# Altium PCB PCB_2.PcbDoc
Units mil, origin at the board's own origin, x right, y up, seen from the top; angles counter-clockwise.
Board outline 5950 x 2265 mil, 6 copper layers (Top Layer 3, Top Layer 2, Top Layer 1, Bottom Layer 1, Bottom Layer 2, Bottom Layer 3), stack 32.068 mil thick; 9 components, 19 nets, 173 pads, 11 vias.
Unrouted connection lines stored in the file: 1.
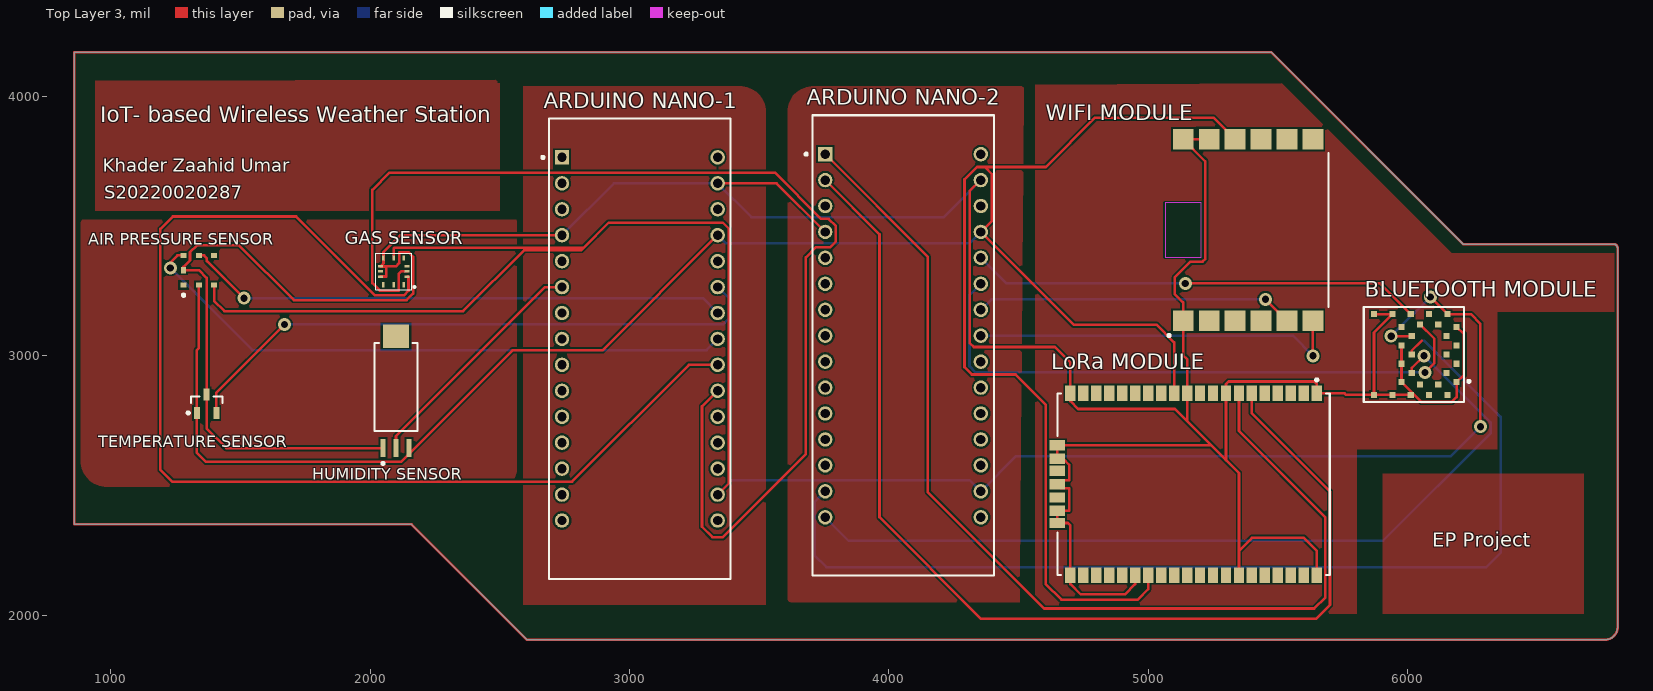
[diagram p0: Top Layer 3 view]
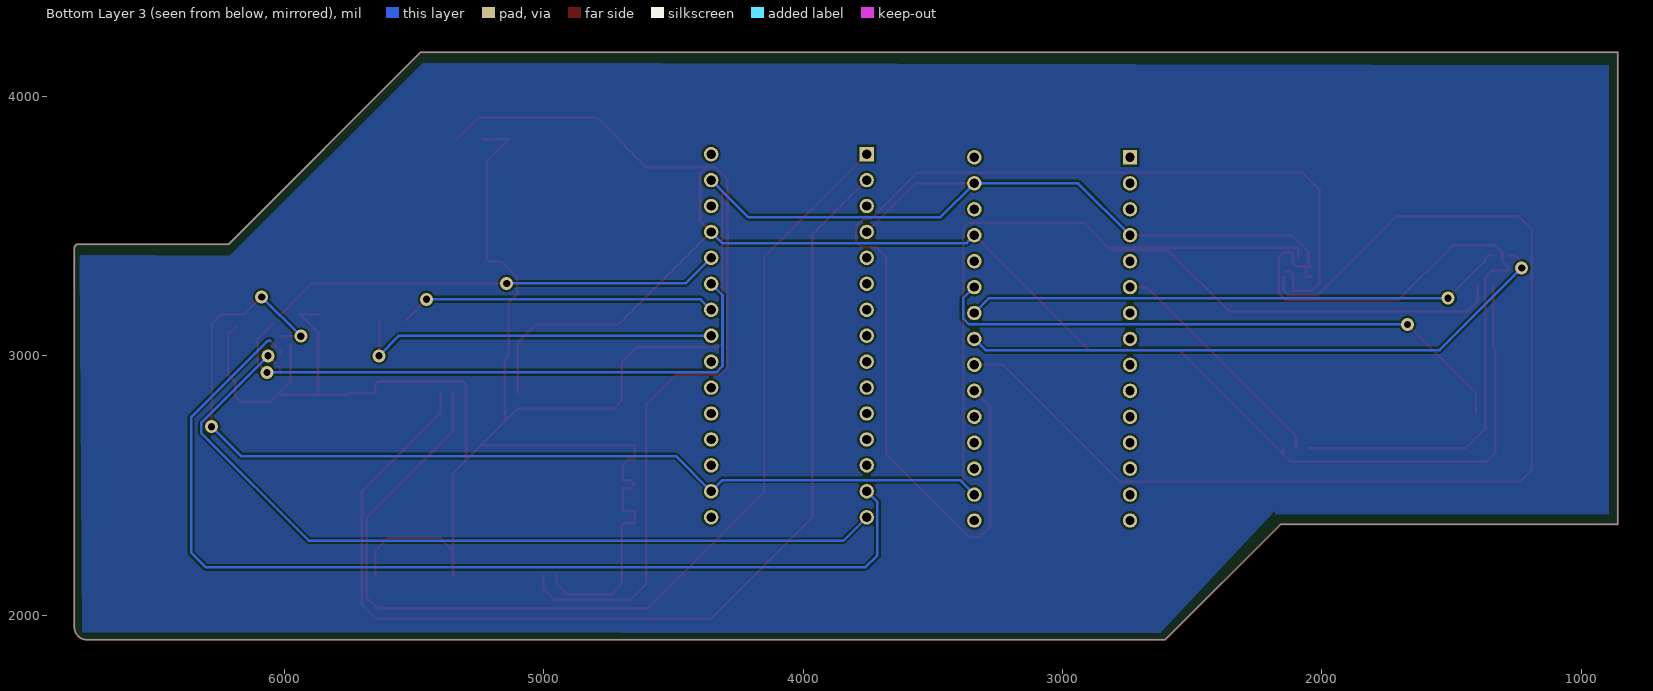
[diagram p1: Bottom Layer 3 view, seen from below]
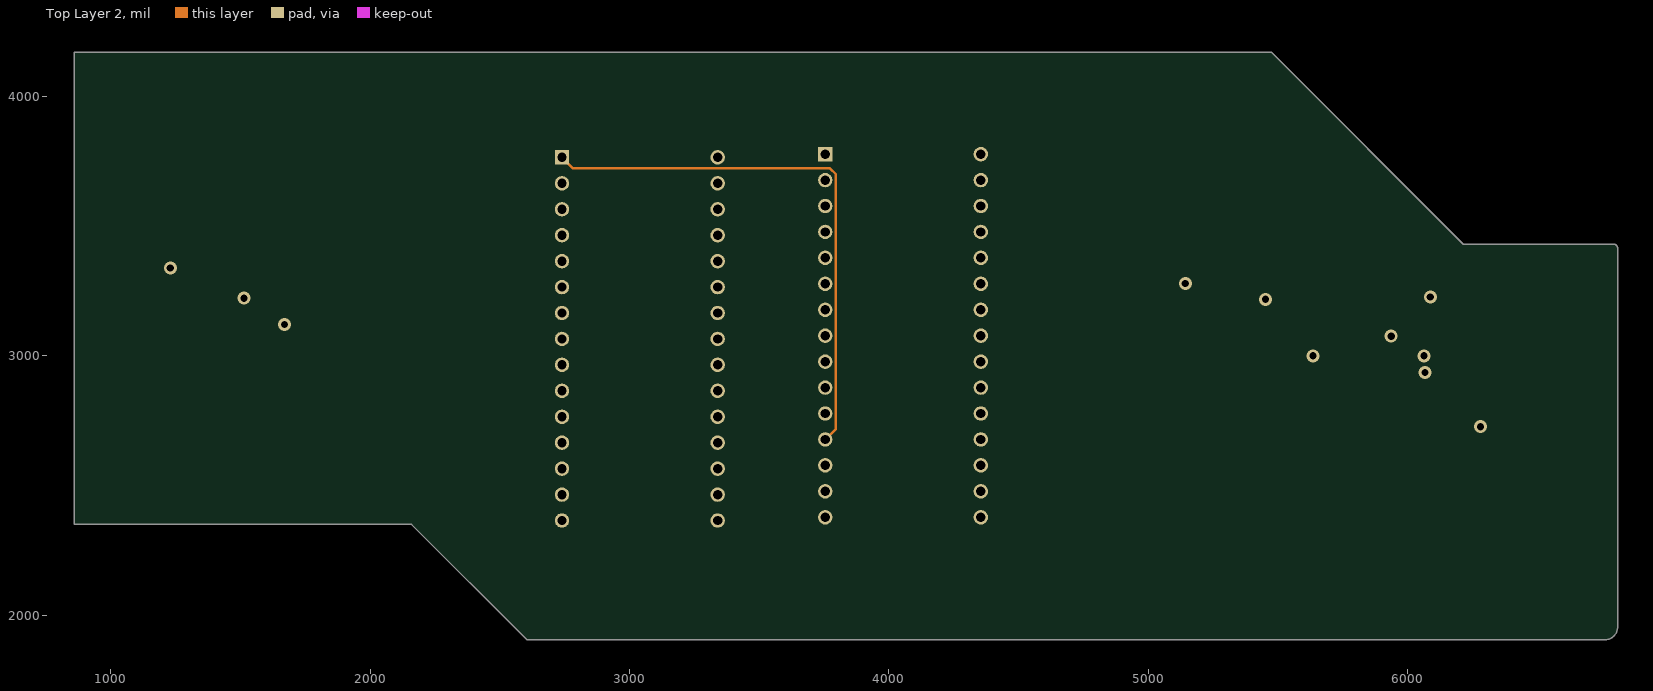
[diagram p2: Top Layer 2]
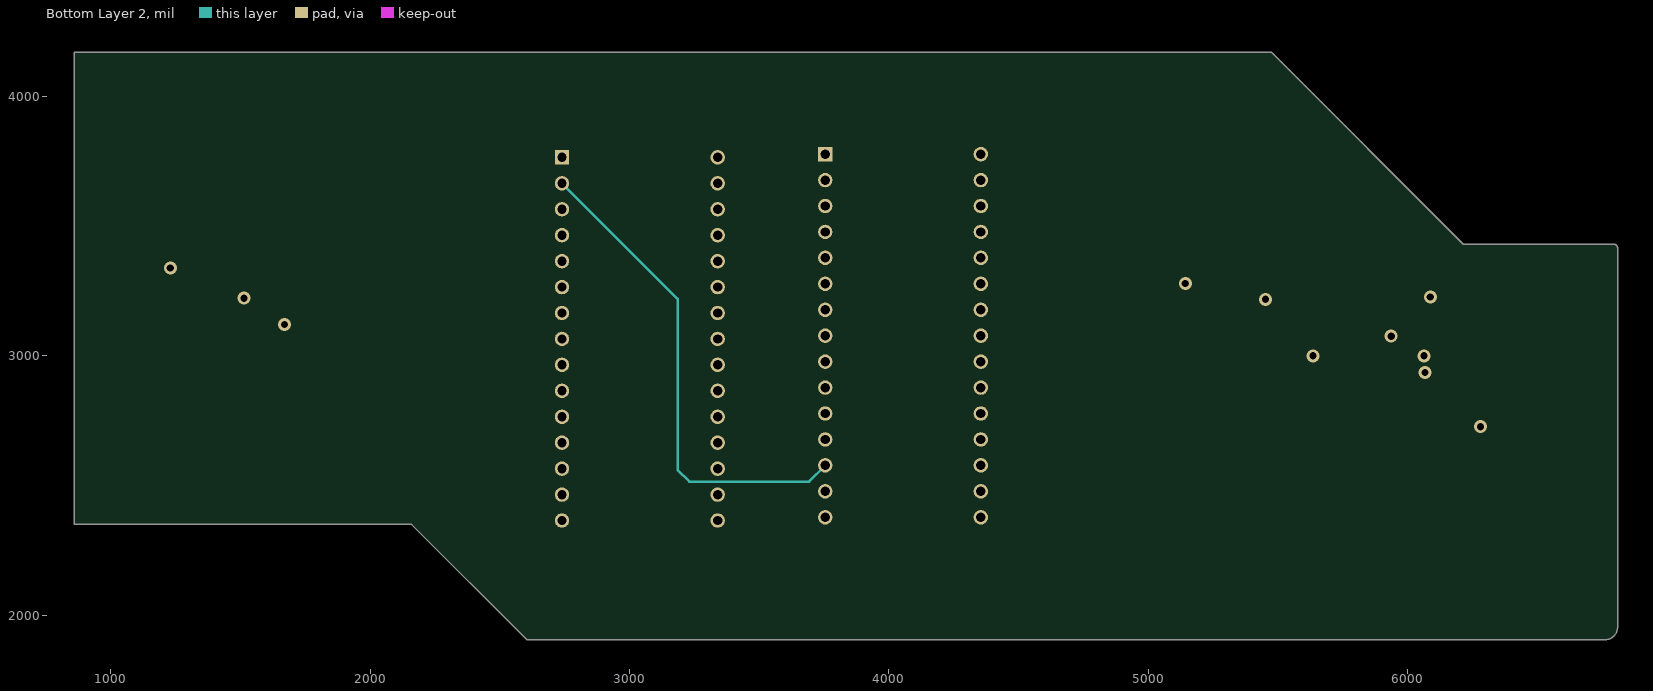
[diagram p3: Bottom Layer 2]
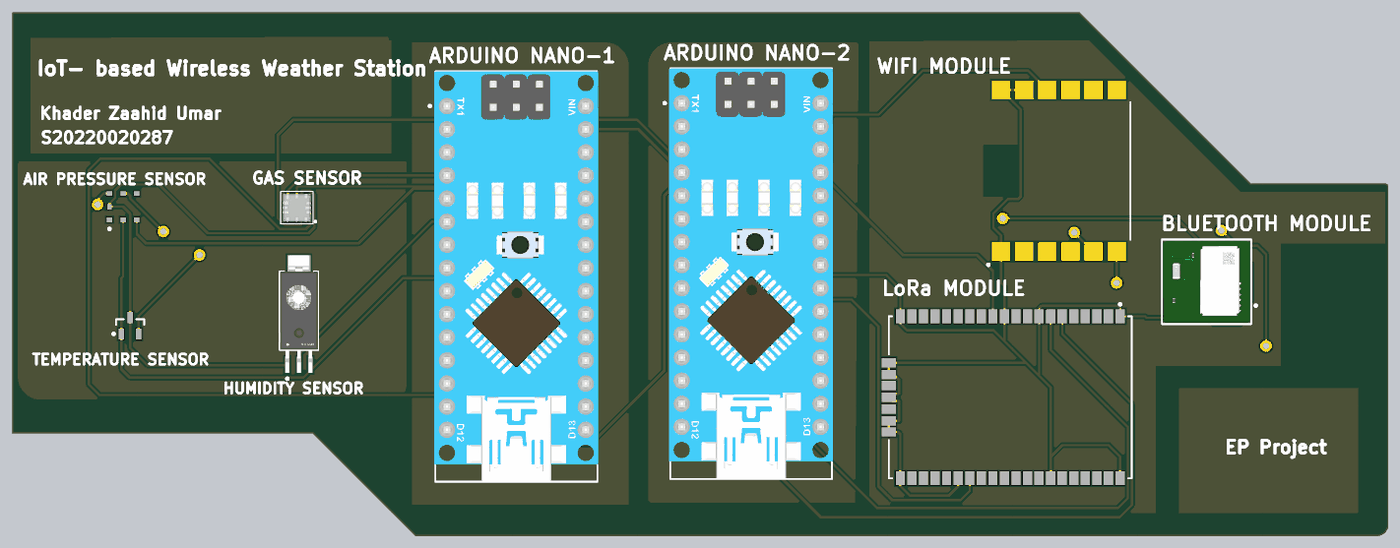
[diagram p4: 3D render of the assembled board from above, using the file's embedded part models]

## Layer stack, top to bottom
Top Solder: solder mask 1, SM-002, Dk 4
Top Layer 3: signal copper 1.378
Dielectric 6: prepreg 2.8, PP-006, Dk 4.1
Top Layer 2: signal copper 1.378
Dielectric 4: prepreg 2.8, PP-006, Dk 4.1
Top Layer 1: signal copper 1.378
Dielectric 1: dielectric 12.6, FR-4, Dk 4.8
Bottom Layer 1: signal copper 1.378
Dielectric 5: prepreg 2.8, PP-006, Dk 4.1
Bottom Layer 2: signal copper 1.378
Dielectric 7: prepreg 2.8, PP-006, Dk 4.1
Bottom Layer 3: signal copper 1.378
Bottom Solder: solder mask 1, SM-002, Dk 4

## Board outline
2160,2350 2605,1905 6760,1905 ccw(c6760,1955) 6810,1955 6810,3415 ccw(c6795,3415) 6795,3430 6215,3430 5475,4170 860,4170 860,2350

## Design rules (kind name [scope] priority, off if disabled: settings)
Clearance [All] p1: gap=8 ignorepadtopadclearanceinfootprint=FALSE
PolygonConnect [All] p1: connectstyle=Relief reliefconductorwidth=10 reliefentries=4 polygonreliefangle="90 Angle" airgapwidth=10
RoutingVias [All] p1: holewidth=28 width=50 viastyle="Through Hole" minholewidth=28 minwidth=50 maxholewidth=28 maxwidth=50
SolderMaskExpansion [All] p1: expansion=4 istentingtop=FALSE
SupplyNets "Schematic Supply Nets_2" [InNet('+5V')] p1: voltage=0.000
SupplyNets "Schematic Supply Nets_1" [InNet('GND')] p2: voltage=0.000
SupplyNets "Schematic Supply Nets" [InNet('3V3')] p3: voltage=0.000
Width [All] p1: maxlimit=10 minlimit=10 preferedwidth=10
30 further rules are at their usual default settings.

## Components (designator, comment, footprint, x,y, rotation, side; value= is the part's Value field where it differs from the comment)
"AIR PRESSURE SENSOR" "BMP180" BOSC-BMP180-7_V 1340,3330 r90 top
"ARDUINO NANO-1" "A000005" FP-A000005-MFG 3040,3027.5 r0 top
"ARDUINO NANO-2" "A000005" FP-A000005-MFG 4055,3040 r0 top
"BLUETOOTH MODULE" "ENW-89846A1KF" FP-ENW-89846A1KF-MFG 6024.02,3005 r90 top
"GAS SENSOR" "ZMOD4510AI1V" "ZMODxxxx 12 Leads- LGG12" 2091.18,3325.32 r90 top
"HUMIDITY SENSOR" "HIH-5031-001" FP-HIH-5031-001-MFG 2100,2880 r0 top
"LoRa MODULE" "RN2483-I/RM095" MCHP-RN2483-47_V 5175,2505 r90 top
"TEMPERATURE SENSOR" "TC1047AVNBTR" SOT-23-NB3_L 1370,2815 r90 top
"WIFI MODULE" "MRF24J40MA-I/RM" MRF24J40MA 5065,3485 r90 top

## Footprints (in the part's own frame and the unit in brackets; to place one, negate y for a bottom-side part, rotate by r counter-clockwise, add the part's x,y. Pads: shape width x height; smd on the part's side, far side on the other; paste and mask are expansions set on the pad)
BOSC-BMP180-7_V [mm] "LGA, 7-Leads, Body 3.9x3.8mm, Pitch 1.5mm"
  rect 0.5x0.6 smd: 1(-1.45,1.5) 2(-1.45,0) 3(-1.45,-1.5) 4(1.45,-1.5) 5(1.45,0) 6(1.45,1.5)
  rect 0.6x0.5 smd: 7(0,1.5)
  silkscreen extent -2.57,1.37 -2.33,1.62, body extent -1.85,-1.95 1.85,1.95, height 1
FP-A000005-MFG [mil]
  rect 55.67x55.67 hole 35.98 paste-99999 mask+0: 1(-300,737.5)
  round 55.67 hole 35.98 paste-99999 mask+0: 2(-300,637.5) 3(-300,537.5) 4(-300,437.5) 5(-300,337.5) 6(-300,237.5) 7(-300,137.5) 8(-300,37.5) 9(-300,-62.5) 10(-300,-162.5) 11(-300,-262.5) 12(-300,-362.5) 13(-300,-462.5) 14(-300,-562.5) 15(-300,-662.5) 16(300,-662.5) 17(300,-562.5) 18(300,-462.5) 19(300,-362.5) 20(300,-262.5) 21(300,-162.5) 22(300,-62.5) 23(300,37.5) 24(300,137.5) 25(300,237.5) 26(300,337.5) 27(300,437.5) 28(300,537.5) 29(300,637.5) 30(300,737.5)
  silkscreen extent -379,-888 350,888, body extent -354,-891 354,891, height 10
FP-ENW-89846A1KF-MFG [mm]
  rect 0.6x0.6 smd paste+0 mask+0: 1(-2.7,-4.2) 2(-1.8,-3.2) 3(-0.9,-4.2) 4(0,-3.2) 5(0.9,-4.2) 6(1.8,-3.2) 7(2.7,-4.2) 8(3.95,-3.3) 9(2.95,-2.4) 10(3.95,-1.5) 11(2.95,-0.6) 12(3.95,0.3) 13(2.7,1.2) 14(1.8,0.2) 15(0.9,1.2) 16(0,0.2) 17(-0.9,1.2) 18(-1.8,0.2) 19(-2.7,1.2) 20(-3.95,0.3) 21(-2.95,-0.6) 22(-3.95,-1.5) 23(-2.95,-2.4) 24(-3.95,-3.3) A(-3.95,2.1) B(3.95,2.1) C(-3.95,3.9) D(3.95,3.9)
  silkscreen extent -4.65,-5.53 4.65,4.9, body extent -4.75,-5 4.75,5, height 0.25
FP-HIH-5031-001-MFG [mm]
  rect 0.51x1.78 smd paste+0 mask+0: 1(-1.27,-5.97) 2(0,-5.97) 3(1.27,-5.97)
  rect 2.54x2.29 smd paste+0 mask+0: 4(0,4.955)
  silkscreen extent -2.11,-7.6 2.11,4.32, body extent -2.21,-6.96 2.21,6.2, height 0.25
MCHP-RN2483-47_V [mil] "47-Leads, Body 26.67x17.8mm, Pitch 1.27mm"
  rect 60x40 smd mask+3.94: 1(350.39,-475) 2(350.39,-425) 3(350.39,-375) 4(350.39,-325) 5(350.39,-275) 6(350.39,-225) 7(350.39,-175) 8(350.39,-125) 9(350.39,-75) 10(350.39,-25) 11(350.39,25) 12(350.39,75) 13(350.39,125) 14(350.39,175) 15(350.39,225) 16(350.39,275) 17(350.39,325) 18(350.39,375) 19(350.39,425) 20(350.39,475) 28(-350.39,475) 29(-350.39,425) 30(-350.39,375) 31(-350.39,325) 32(-350.39,275) 33(-350.39,225) 34(-350.39,175) 35(-350.39,125) 36(-350.39,75) 37(-350.39,25) 38(-350.39,-25) 39(-350.39,-75) 40(-350.39,-125) 41(-350.39,-175) 42(-350.39,-225) 43(-350.39,-275) 44(-350.39,-325) 45(-350.39,-375) 46(-350.39,-425) 47(-350.39,-475)
  rect 40x60 smd mask+3.94: 21(149.61,525) 22(98.43,525) 23(51.18,525) 24(0,525) 25(-51.18,525) 26(-102.36,525) 27(-149.61,525)
  silkscreen extent -350,-525 407,525, body extent -350,-525 350,525, height 118
MRF24J40MA [mil] "SM Module; 12 Leads; Body 27.9x17.8x1.7mm (LxWxH), Microchip Recommended"
  rect 80x80 smd paste-159.45 mask+2: 1(-350,-70) 2(-350,-170) 3(-350,-270) 4(-350,-370) 5(-350,-470) 6(-350,-570) 7(350,-570) 8(350,-470) 9(350,-370) 10(350,-270) 11(350,-170) 12(350,-70)
  Top Layer 3 keep-out region: -105,-140 105,-140 105,0 -105,0
  silkscreen extent -411,-630 298,-11, body extent -350,-630 350,470, height 67
SOT-23-NB3_L [mm] "SOT23, 3-Leads, Body 2.9x1.3mm, Pitch 0.95mm, Lead Span 2.4mm, IPC High Density"
  rect 1.2x0.6 smd: 1(-0.9,0.95) 2(-0.9,-0.95) 3(0.9,0)
  silkscreen extent -1.02,-1.55 0.7,1.92, body extent -0.7,-1.52 0.7,1.53, height 1.12
"ZMODxxxx 12 Leads- LGG12" [mm] "LGA 3.00x3.00x0.70 mm 0.50mm Pitch"
  rect 0.25x0.5 smd: 1(-0.5,-1.3) 2(0,-1.3) 3(0.5,-1.3) 7(0.5,1.3) 8(0,1.3) 9(-0.5,1.3)
  rect 0.5x0.25 smd: 4(1.3,-1) 5(1.3,0) 6(1.3,1) 10(-1.3,1) 11(-1.3,0) 12(-1.3,-1)
  silkscreen extent -1.78,-2.13 1.78,1.78, body extent -1.5,-1.5 1.5,1.5, height 0.78

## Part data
"AIR PRESSURE SENSOR": library part CMP-2000-05074-1, "Digital Pressure Sensor, 1.8 to 3.6 V, -40 to 85 degC, 7-Pin LGA, RoHS", Manufacturer="Bosch Sensortec", Operating Pressure=4.35PSI~15.95PSI(30kPa~110kPa), Operating Temperature=-40degC~85degC, Package / Case=7-VLGA, Standard Package=5,000, Supplier Device Package=7-LGA, Voltage - Supply=1.62V~3.6V
"ARDUINO NANO-1" "ARDUINO NANO-2": library part CMP-189986-000002-1, "ARDUINO NANO ATMEGA328 EVAL BRD", Operating Supply Voltage=12V, Package Quantity=50
"BLUETOOTH MODULE": library part CMP-05527-000002-1, "RF TXRX MOD BLUETOOTH CHIP ANT", Ambient Temperature Range High=+85°C, Ambient Temperature Range Low=-40°C, Manufacturer=Panasonic, Max Frequency=2.4GHz, Max Supply Voltage=3.3V, Min Supply Voltage=2.35V, Package=0, Receiving Current=4.9mA, Temperature="-40°C to +85°C"
"GAS SENSOR": library part CMP-00572-100129191-1, "ZMOD4510AI1V ZMOD4510 Series 3.6 V 11 mA Gas Sensor Module for Outdoor Air Quality - LGA-12"
"HUMIDITY SENSOR": library part CMP-11179-000003-1, "SENSOR HUMIDITY 5V ANALOG 3% SMD", Case/Package=SMD/SMT, Max Operating Temperature=85°C, Max Supply Voltage=5.5V, Min Operating Temperature=-40°C, Min Supply Voltage=2.7V, Nominal Supply Current=500uA, Operating Supply Current=200uA, Operating Supply Voltage=3.3V, Package Quantity=1
"LoRa MODULE": library part CMP-2000-05219-1, "Low-Power Long Range LoRa(TM) Technology Transceiver Module, 2.1 to 3.6 V, -40 to 85 degC, 47-Pin SMD, RoHS", Manufacturer=Microchip, Maximum Operating Supply Voltage=3.6V, Maximum Operating Temperature=+85degC, Minimum Operating Supply Voltage=2.1V, Minimum Operating Temperature=-40degC, Operating Band Frequency Range=438,868MHz, Operating Supply Voltage Range=2.1to3.6V, Operating Temperature Range=-40to+85degC, Package Type=Module
"TEMPERATURE SENSOR": library part CMP-0192-00223-1, "Precision Temperature-to-Voltage Converter, 3-Pin SOT-23, Extended Temperature, Tape and Reel"
"WIFI MODULE": library part CMP-0191-00063-1, "2.4 GHz IEEE Std. 802.15.4, RF Transceiver 12-Pin Module, Industrial Temperature"

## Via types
v1: diameter 50, hole 28, Top Layer 3 to Bottom Layer 3, 11 vias

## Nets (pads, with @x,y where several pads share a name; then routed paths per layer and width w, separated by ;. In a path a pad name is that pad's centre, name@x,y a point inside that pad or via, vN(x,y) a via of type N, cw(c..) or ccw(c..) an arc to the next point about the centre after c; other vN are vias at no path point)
3V3: "AIR PRESSURE SENSOR.3" "ARDUINO NANO-1.17" "ARDUINO NANO-2.17" "BLUETOOTH MODULE.8" "BLUETOOTH MODULE.14" "GAS SENSOR.5" | length 8038
  Top Layer 3 w10: 1399.06,3272.91 1399.06,3211 1438.06,3172 2359,3172 2595,3408 2815,3408 2824.34,3417.34 ; 2091.18,3376.5 2091.18,3413.89 2094.63,3417.34 2824.34,3417.34 ; 3340,2465 3383,2508 3383,3490 3360,3513 2920,3513 2824.34,3417.34 ; v1(5937,3075.87) 6016.14,3075.87 ; v1(6087.79,3226.66) 6153.94,3160.51 6244,3160.51 6281,3123.51 v1(6281,2727)
  Bottom Layer 3 w10: 3340,2465 3396,2521 4311.5,2521 4355,2477.5 4490.5,2613 6167,2613 v1(6281,2727) ; v1(5937,3075.87) v1(6087.79,3226.66)
+5V: "AIR PRESSURE SENSOR.2" "ARDUINO NANO-1.27" "ARDUINO NANO-2.27" "HUMIDITY SENSOR.3" "LoRa MODULE.12" "LoRa MODULE.34" "TEMPERATURE SENSOR.1" "WIFI MODULE.10" | length 8955.6
  Top Layer 3 w10: 1340,3272.91 1340,3029.4 1332.6,3022 1332.6,2779.57 1332.6,2626 1367.6,2591 2119,2591 2150,2622 ; 2150,2644.96 2150,2622 ; 3340,3465 2896,3021 2549,3021 2161.48,2633.48 2150,2622 ; 5000,2154.61 5000,2100 4960,2060 4665,2060 4605,2120 4605,2812 4489,2928 4320,2928 4292,2956 4292,3680 4340,3728 4370,3728 ; 5100,2855.39 5100,3052 5032,3120 4712.5,3120 4355,3477.5 4398,3520.5 4398,3700 4370,3728 ; 5335,3835 5252,3918 4795.5,3918 4605.5,3728 4370,3728
  Bottom Layer 3 w10: 3340,3465 3370.34,3434.66 4312.16,3434.66 4355,3477.5
GND: "AIR PRESSURE SENSOR.7" "ARDUINO NANO-1.4" "ARDUINO NANO-1.29" "ARDUINO NANO-2.4" "ARDUINO NANO-2.29" "BLUETOOTH MODULE.1" "BLUETOOTH MODULE.7" "BLUETOOTH MODULE.15" "BLUETOOTH MODULE.17" "BLUETOOTH MODULE.19" "BLUETOOTH MODULE.20" "BLUETOOTH MODULE.A" "BLUETOOTH MODULE.B" "BLUETOOTH MODULE.C" "BLUETOOTH MODULE.D" "GAS SENSOR.6" "GAS SENSOR.7" "GAS SENSOR.9" "HUMIDITY SENSOR.1" "LoRa MODULE.1" "LoRa MODULE.8" "LoRa MODULE.11" "LoRa MODULE.20" "LoRa MODULE.21" "LoRa MODULE.22" "LoRa MODULE.24" "LoRa MODULE.26" "LoRa MODULE.27" "LoRa MODULE.28" "LoRa MODULE.33" "LoRa MODULE.41" "LoRa MODULE.47" "TEMPERATURE SENSOR.3" "WIFI MODULE.1" "WIFI MODULE.11" "WIFI MODULE.12" | length 13850.3
  Top Layer 3 w10: 2040,3305.63 2063,3305.63 2063,3344 2041,3344 2040,3345 ; 2050,2644.96 2050,2644 1446,2644 1370,2720 1370,2850.43 1370,3300 1340,3330 1280.94,3330 1280.94,3342.94 1306,3368 1306,3400 1332,3426 1495,3426 1706,3215 2141.47,3215 2166.47,3240 2166.47,3380.87 2148,3399.34 2112,3399.34 2112,3357 2100,3345 2040,3345 ; 2740,3465 2116.81,3465 2051.81,3400 2051.81,3376.5 2051.81,3356.81 2040,3345 ; 3340,3665 3567.5,3665 3755,3477.5 ; 4355,3677.5 4312,3634.5 4312,3050 4328,3034 4640,3034 4700,2974 4700,2855.39 4700,2825 4730,2795 5103,2795 5150,2748 ; 4950,2154.61 4950,2120 4910,2080 4740,2080 4700,2120 4700,2154.61 4700,2345.39 4690,2355.39 4650,2355.39 4650,2402.64 4695,2402.64 4695,2489 4666,2489 4650,2505 4666,2521 4695,2521 4695,2580 4671.57,2603.43 4650,2603.43 4650,2654.61 5243.39,2654.61 ; 5235,3835 5135,3835 5220,3750 5220,3373 5210,3363 5163.99,3363 5102.37,3301.38 5102.37,3239.01 5135,3206.38 5135,3135 5135,3002 5150,2987 5150,2855.39 5150,2748 ; 5350,2154.61 5350,2248 ; 5650,2154.61 5650,2248 5600,2298 5400,2298 5350,2248 ; 5870.47,3160.51 5941.34,3160.51 5870.47,3089.65 5870.47,2849.49 ; 5976.77,3040.43 5976.77,2969.57 5976.77,2898.7 6019.09,2856.38 ; 6189.37,3111.3 6217,3083.67 6217,2926.33 6189.37,2898.7 6189.37,2841.37 6170,2822 6053.47,2822 6019.09,2856.38 ; 5150,2748 5243.39,2654.61 ; 5243.39,2654.61 5300,2598 ; 5300,2598 5350,2548 5350,2248 ; 5300,2598 5300,2855.39 5300,2891 5310,2901 5640,2901 5650,2891 5650,2855.39 5757,2855.39 5762.91,2849.49 5870.47,2849.49 ; 5870.47,2849.49 5941.34,2849.49 6012.2,2849.49 6019.09,2856.38
  Bottom Layer 3 w10: 2740,3465 2940,3665 3340,3665 3470.34,3534.66 4212.16,3534.66 4355,3677.5
"NetAIR PRESSURE SENSOR_5": "AIR PRESSURE SENSOR.5" "ARDUINO NANO-1.24" | length 2098.5
  Top Layer 3 w10: 1340,3387.09 1360,3387.09 1371,3376.09 1371,3365 v1(1514,3222)
  Bottom Layer 3 w10: v1(1514,3222) 3283,3222 3340,3165
"NetAIR PRESSURE SENSOR_6": "AIR PRESSURE SENSOR.6" "ARDUINO NANO-1.23" | length 2342.1
  Top Layer 3 w10: v1(1230,3339) 1230,3360 1257.09,3387.09 1280.94,3387.09
  Bottom Layer 3 w10: v1(1230,3339) 1546.84,3022.16 3297.16,3022.16 3340,3065
"NetARDUINO NANO-1_1": "ARDUINO NANO-1.1" "ARDUINO NANO-2.12" | length 2122.4
  Top Layer 2 w10: 2740,3765 2782,3723 3773,3723 3796,3700 3796,2718.5 3755,2677.5
"NetARDUINO NANO-1_2": "ARDUINO NANO-1.2" "ARDUINO NANO-2.13" | length 1903.3
  Bottom Layer 2 w10: 2740,3665 3186,3219 3186,2560 3231,2515 3692.5,2515 3755,2577.5
"NetARDUINO NANO-1_6": "ARDUINO NANO-1.6" "HUMIDITY SENSOR.2" | length 923.8
  Top Layer 3 w10: 2100,2644.96 2100,2691 2674,3265 2740,3265
"NetARDUINO NANO-1_21": "ARDUINO NANO-1.21" "GAS SENSOR.2" | length 4530.7
  Top Layer 3 w10: 2142.36,3325.32 2120,3325.32 2110,3315.32 2110,3251 2038,3251 2009,3280 2009,3640 2075,3706 3561,3706 3739,3528 3768,3528 3796,3500 3796,3440 3775,3419 3720,3419 3680,3379 3680,2621 3360,2301 3320,2301 3280,2341 3280,2805 3340,2865
"NetARDUINO NANO-1_22": "ARDUINO NANO-1.22" "GAS SENSOR.1" | length 4452.3
  Top Layer 3 w10: 2142.36,3305.63 2148.47,3305.63 2148.47,3251.29 2130.18,3233 2019,3233 1715,3537 1240,3537 1192,3489 1192,2560 1237,2515 2779,2515 3229,2965 3340,2965
"NetARDUINO NANO-1_25": "ARDUINO NANO-1.25" "TEMPERATURE SENSOR.2" | length 2311.3
  Top Layer 3 w10: 1407.4,2779.57 1407.4,2858 v1(1670.4,3121)
  Bottom Layer 3 w10: v1(1670.4,3121) 3360,3121 3383,3144 3383,3222 3340,3265
"NetARDUINO NANO-2_1": "ARDUINO NANO-2.1" "LoRa MODULE.7" | length 4127.2
  Top Layer 3 w10: 3755,3777.5 4150,3382.5 4150,2475 4599,2026 5640,2026 5683,2069 5683,2377 5350,2710 5350,2855.39
"NetARDUINO NANO-2_2": "ARDUINO NANO-2.2" "LoRa MODULE.6" | length 4247.9
  Top Layer 3 w10: 3755,3677.5 3964,3468.5 3964,2378 4356,1986 5647,1986 5701,2040 5701,2477 5400,2778 5400,2855.39
"NetARDUINO NANO-2_14": "ARDUINO NANO-2.14" "BLUETOOTH MODULE.16" | length 3969.7
  Top Layer 3 w10: 6016.14,3005 6016.14,3020 6054.14,3058
  Bottom Layer 3 w10: 3755,2477.5 3714,2436.5 3714,2231 3760,2185 6304,2185 6359,2240 6359,2764 6065,3058 6054.14,3058
"NetARDUINO NANO-2_15": "ARDUINO NANO-2.15" "BLUETOOTH MODULE.18" | length 3264.7
  Top Layer 3 w10: 6016.14,2934.13 6016.14,2953.14 v1(6063,3000)
  Bottom Layer 3 w10: 3755,2377.5 3845.5,2287 5906,2287 6320,2701 6320,2743 v1(6063,3000)
"NetARDUINO NANO-2_23": "ARDUINO NANO-2.23" "WIFI MODULE.6" | length 1447.1
  Top Layer 3 w10: v1(5635,3000) 5635,3135
  Bottom Layer 3 w10: 4355,3077.5 5557.5,3077.5 v1(5635,3000)
"NetARDUINO NANO-2_24": "ARDUINO NANO-2.24" "WIFI MODULE.5" | length 1231.2
  Top Layer 3 w10: v1(5452,3218) 5535,3135
  Bottom Layer 3 w10: 4355,3177.5 4395.5,3218 v1(5452,3218)
"NetARDUINO NANO-2_25": "ARDUINO NANO-2.25" "BLUETOOTH MODULE.11" | length 2324.7
  Top Layer 3 w10: 6047.64,3121.14 6103,3065.78 6103,2972 v1(6067,2936)
  Bottom Layer 3 w10: 4355,3277.5 4311,3233.5 4311,2960 4335,2936 v1(6067,2936)
"NetARDUINO NANO-2_26": "ARDUINO NANO-2.26" "BLUETOOTH MODULE.12" | length 1747.1
  Top Layer 3 w10: v1(5143,3279) 5893.72,3279 6012.2,3160.51
  Bottom Layer 3 w10: 4355,3377.5 4453.5,3279 v1(5143,3279)
pads on no net: "AIR PRESSURE SENSOR.1" "AIR PRESSURE SENSOR.4" "ARDUINO NANO-1.3" "ARDUINO NANO-1.5" "ARDUINO NANO-1.7" "ARDUINO NANO-1.8" "ARDUINO NANO-1.9" "ARDUINO NANO-1.10" "ARDUINO NANO-1.11" "ARDUINO NANO-1.12" "ARDUINO NANO-1.13" "ARDUINO NANO-1.14" "ARDUINO NANO-1.15" "ARDUINO NANO-1.16" "ARDUINO NANO-1.18" "ARDUINO NANO-1.19" "ARDUINO NANO-1.20" "ARDUINO NANO-1.26" "ARDUINO NANO-1.28" "ARDUINO NANO-1.30" "ARDUINO NANO-2.3" "ARDUINO NANO-2.5" "ARDUINO NANO-2.6" "ARDUINO NANO-2.7" "ARDUINO NANO-2.8" "ARDUINO NANO-2.9" "ARDUINO NANO-2.10" "ARDUINO NANO-2.11" "ARDUINO NANO-2.16" "ARDUINO NANO-2.18" "ARDUINO NANO-2.19" "ARDUINO NANO-2.20" "ARDUINO NANO-2.21" "ARDUINO NANO-2.22" "ARDUINO NANO-2.28" "ARDUINO NANO-2.30" "BLUETOOTH MODULE.2" "BLUETOOTH MODULE.3" "BLUETOOTH MODULE.4" "BLUETOOTH MODULE.5" "BLUETOOTH MODULE.6" "BLUETOOTH MODULE.9" "BLUETOOTH MODULE.10" "BLUETOOTH MODULE.13" "BLUETOOTH MODULE.21" "BLUETOOTH MODULE.22" "BLUETOOTH MODULE.23" "BLUETOOTH MODULE.24" "GAS SENSOR.3" "GAS SENSOR.4" "GAS SENSOR.8" "GAS SENSOR.10" "GAS SENSOR.11" "GAS SENSOR.12" "HUMIDITY SENSOR.4" "LoRa MODULE.2" "LoRa MODULE.3" "LoRa MODULE.4" "LoRa MODULE.5" "LoRa MODULE.9" "LoRa MODULE.10" "LoRa MODULE.13" "LoRa MODULE.14" "LoRa MODULE.15" "LoRa MODULE.16" "LoRa MODULE.17" "LoRa MODULE.18" "LoRa MODULE.19" "LoRa MODULE.23" "LoRa MODULE.25" "LoRa MODULE.29" "LoRa MODULE.30" "LoRa MODULE.31" "LoRa MODULE.32" "LoRa MODULE.35" "LoRa MODULE.36" "LoRa MODULE.37" "LoRa MODULE.38" "LoRa MODULE.39" "LoRa MODULE.40" "LoRa MODULE.42" "LoRa MODULE.43" "LoRa MODULE.44" "LoRa MODULE.45" "LoRa MODULE.46" "WIFI MODULE.2" "WIFI MODULE.3" "WIFI MODULE.4" "WIFI MODULE.7" "WIFI MODULE.8" "WIFI MODULE.9"
copper on no net: | length 15707.9
  Top Layer 3 w10: 860,2350 860,4170 5475,4170 6215,3430 6795,3430 cw(c6795,3415) 6810,3415 6810,1955 cw(c6760,1955) 6760,1905 2605,1905 2160,2350 860,2350

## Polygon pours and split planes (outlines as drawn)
no net on Top Layer 3 "NONET_L-01_P-001" (solid, pour order 11): 940,4060 940,3560 2500,3560 2500,4050 2490,4050 2490,4065
no net on Top Layer 3 "NONET_L-01_P-001" (solid, pour order 6): 4565,4045 4565,2005 5805,2005 5805,2640 6345,2640 6345,3170 6800,3170 6800,3395 6170,3395 5515,4050
no net on Top Layer 3 "NONET_L-01_P-001" (solid, pour order 4): 4520,4040 3710,4040 ccw(c3710,3940) 3610,3940 3610,2065 ccw(c3625,2065) 3625,2050 4505,2050
no net on Top Layer 3 "NONET_L-01_P-001" (solid, pour order 3): 2590,4040 3425,4040 cw(c3425,3940) 3525,3940 3525,2040 2590,2040
no net on Top Layer 3 "NONET_L-01_P-001" (solid, pour order 1): 885,3515 885,2595 ccw(c985,2595) 985,2495 2500,2495 ccw(c2500,2560) 2565,2560 2565,3520 ccw(c2560,3520) 2560,3525 890,3525
no net on Top Layer 3 "NONET_L-01_P-001" (solid, pour order 7): 5905,2545 5905,2005 6680,2005 6680,2545
no net on Bottom Layer 3 "NONET_L-01_P-001" (solid, pour order 9): 895,4120 895,2390 2180,2390 2180,2405 2625,1930 6780,1935 6790,3390 6210,3385 5465,4130

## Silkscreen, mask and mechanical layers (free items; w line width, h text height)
Board Layer Stack Top Overlay:
  text "IoT- based Wireless Weather Station" at 960,3900 h60
  text "Khader Zaahid Umar" at 970,3710 h50
  text "S20220020287" at 975,3605 h50
  text "EP Project" at 6095,2263.33 h55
